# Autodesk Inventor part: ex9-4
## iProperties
Shininess: 64.0
Length Units: 11272
Angle Units: 11279
Time Units: 11290
Mass Units: 11286
Length Display Precision: 3
Angle Display Precision: 2
Compacted: True
Part Number: ex9-4
Document SubType Name: Sheet Metal
Created: 2002-11
Designer: Elise Moss
Density: 0.0
Volumn: 0.0
Area: 0.0
PropertySet Name: Model Information
Control State: 0
Master: False
Checked Out: False
Author: Elise Moss
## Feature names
1. Plate1
2. Bend1
3. Plate2
4. Bend2
5. Cut1
